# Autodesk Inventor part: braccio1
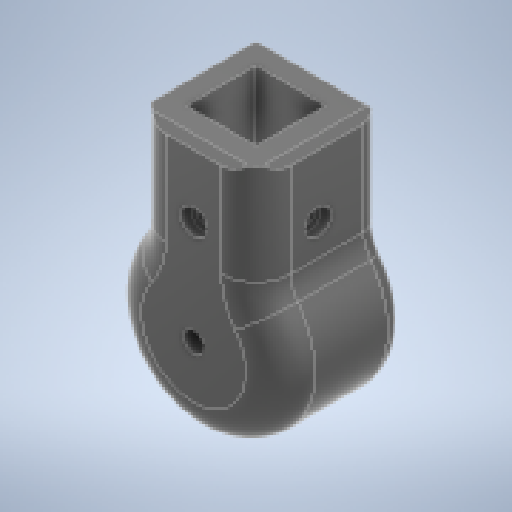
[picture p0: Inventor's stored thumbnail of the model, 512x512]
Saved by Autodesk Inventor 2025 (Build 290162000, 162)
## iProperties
Created: 2026-03
Part Number: braccio1
Material: Plastica ABS
Document SubType Name: Modeling
Designer: R5800u
Density: 1.06 g/cm^3
Appearance: Liscia - Nero
Author: R5800u
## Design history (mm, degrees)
sketch "Schizzo1"
  geometry: L1 (-2.646, 3)-(2.646, 3); C1 r 25 at (0, 0); A1 r 4 centre (0, 0) between (-2.646, 3) and (2.646, 3); 1 further point
  constraints: 2 centre point, 2 coincident, 2 end point, 2 point on circle, 1 horizontal
  dimensions: "d0" = 50 diameter of C1; "d1" = 8 diameter of A1; "d2" = 3 distance from line of point (0, 0) L1
extrude "Estrusione1" new body sketch "Schizzo1" stored distance "d3" = 36; taper "d4" = 0 deg
node "Piano di lavoro1"
sketch "Schizzo2"
  geometry: L1 (18, 18)-(-18, 18); L2 (-18, 18)-(-18, -18); L3 (-18, -18)-(18, -18); L4 (18, -18)-(18, 18); L5 (18, 18)-(-18, -18); L6 (-18, 18)-(18, -18); L7 (10, 10)-(-10, 10); L8 (-10, 10)-(-10, -10); L9 (-10, -10)-(10, -10); L10 (10, -10)-(10, 10); L11 (10, 10)-(-10, -10); L12 (-10, 10)-(10, -10); 1 further point
  constraints: 24 end point, 4 midpoint, 4 parallel, 2 horizontal, 2 perpendicular
  dimensions: "d6" = 36 distance of L3.end L2.end; "d7" = 36 distance of L2.end L1.end; "d8" = 20 distance of L9.end L8.end; "d9" = 20 distance of L8.end L7.end
extrude "Estrusione2" join sketch "Schizzo2" stored distance "d10" = 10; taper "d11" = 0 deg
sketch "Schizzo3"
  geometry: L1 (-10, 50)-(10, 50) reference; L2 (0, 50)-(0, 30); 1 further point
  constraints: 2 end point, 1 midpoint, 1 vertical
  dimensions: "d16" = 20 distance of L2.start L2.end
hole "Foro1" sketch "Schizzo3" at (0, 30) diameter "d17" = 4.3; stored, may be unused: countersink angle "d21" = 90 deg, drill point angle "d23" = 118 deg; dims "d18" = 6, "d19" = 7.5, "d20" = 3, "d22" = 8
pattern_circular "Serie circolare1" dims angle "d25" = 360 deg
chamfer "Smusso2" distance "d27" = 2; stored, may be unused: second distance "d28" = 2, angle "d29" = 45 deg
fillet "Raccordo2" dims "d30" = 10
fillet "Raccordo3" dims "d31" = 10
sketch "Schizzo4"
  geometry: A1 r 4 centre (0, 0) between (-2.646, 3) and (2.646, 3) reference; 3 further points
  constraints: 1 coincident, 3 other
extrude "Estrusione3" join sketch "Schizzo4" distance "d32" = 15; taper "d33" = 0 deg
sketch "Schizzo5"
  geometry: A1 r 15 centre (0, 0) between (-12, 9) and (12, 9) reference; 2 further points
  constraints: 1 coincident
hole "Foro2" sketch "Schizzo5" at (0, 0) diameter "d34" = 3.4; stored, may be unused: countersink angle "d38" = 90 deg, drill point angle "d40" = 118 deg; dims "d35" = 6, "d36" = 6, "d37" = 15, "d39" = 8
fillet "Raccordo4" dims "d41" = 5
node "Solido1"
